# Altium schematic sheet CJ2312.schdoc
size 127 x 101 mm
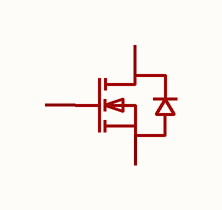
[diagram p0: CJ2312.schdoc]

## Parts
Q?  cj2312  [SOT-23_L2.9-W1.3-P1.90-LS2.4-BR]  (value not drawn)

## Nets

Not connected (* = marked no-connect by the designer): Q? 1(G) 2(S) 3(D)

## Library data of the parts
Q? = cj2312: 数量:1个N沟道;漏源电压(Vdss):20V;连续漏极电流(Id):5A;导通电阻(RDS(on)):41.4mΩ@1.8V;耗散功率(Pd):350mW;阈值电压(Vgs(th)):1V;; Manufacturer: CJ(江苏长电/长晶); AddInBom: yes; ModelId: c62791f0466c4ae2a892c056b845b0ca; ModelName: SOT-23-3P_L2.9-W1.3-H1.0-LS2.4-P0.95; ModelTransform: 98.64468,114.173,0,180,0,0,0.001,-0.002,0; Number: 1个N沟道; Drain to Source Voltage: 20V; Current - Continuous Drain(Id): 5A; Pd - Power Dissipation: 350mW; Gate Threshold Voltage (Vgs(th)): 1V; Input Capacitance(Ciss): 865pF; Reverse Transfer Capacitance (Crss@Vds): 55pF; Type: N沟道; Output Capacitance(Coss): 105pF; Vgs: ±8V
